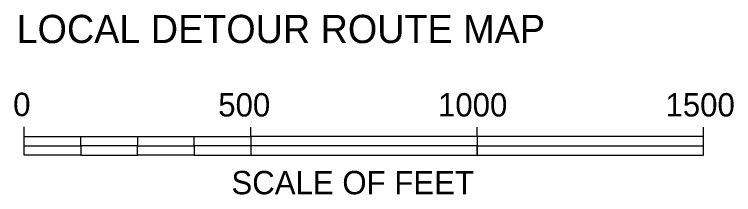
# Model space of a CAD drawing. Extents: x -452339 to 6403467, y -1 to 1814750.
# Drawn here: x -19225 to 6192, y 1556532 to 1562891 of the extents above; entities that cross this region are included whole.
import ezdxf

# ---------------------------------------------------------------- set-up
doc = ezdxf.new("R2010")
doc.units = 0
doc.layers.add('Default', color=7, linetype='Continuous')

msp = doc.modelspace()

# ---------------------------------------------------------------- linework, layer by layer
at = {"layer": 'Default'}
for p, q in [((-18873, 1558583), (-18873, 1558928)), ((-10873, 1558583), (-10873, 1558913)), ((-2874, 1558583), (-2874, 1558913)), ((5126, 1558583), (5126, 1558913)), ((-18873, 1558583), (-16873, 1558583)), ((-18873, 1558253), (-18873, 1558583)), ((-16873, 1558253), (-16873, 1558583)), ((-16873, 1558583), (-14873, 1558583)), ((-14874, 1558583), (-12873, 1558583)), ((-14874, 1558583), (-14874, 1558253)), ((-14873, 1558583), (-14873, 1558253)), ((-12873, 1558253), (-12873, 1558583)), ((-12873, 1558583), (-10873, 1558583)), ((-10873, 1558583), (-10873, 1558253)), ((-2874, 1558583), (-10873, 1558583)), ((-10873, 1558583), (-10873, 1558253)), ((5126, 1558583), (-2874, 1558583)), ((-2874, 1558583), (-2874, 1558253)), ((5126, 1558253), (5126, 1558583)), ((-18873, 1557923), (-18873, 1558253)), ((-18873, 1558253), (-16873, 1558253)), ((-16873, 1558253), (-16873, 1557923)), ((-14873, 1558253), (-16873, 1558253)), ((-16873, 1558253), (-16873, 1558253)), ((-14874, 1557923), (-14874, 1558253)), ((-14874, 1558253), (-12874, 1558253)), ((-14874, 1557923), (-14874, 1558253)), ((-12874, 1558253), (-12874, 1557923)), ((-10873, 1558253), (-12874, 1558253)), ((-12874, 1558253), (-12873, 1558253)), ((-2874, 1558253), (-10873, 1558253)), ((-10873, 1558253), (-10873, 1557923)), ((-2874, 1557923), (-2874, 1558253)), ((-2874, 1558253), (5126, 1558253)), ((-2874, 1558253), (-2874, 1557923)), ((5126, 1557923), (5126, 1558253)), ((-16873, 1557923), (-18874, 1557923)), ((-18874, 1557923), (-18873, 1557923)), ((-16873, 1557923), (-14874, 1557923)), ((-12874, 1557923), (-14874, 1557923)), ((-14874, 1557923), (-14874, 1557923)), ((-12874, 1557923), (-10874, 1557923)), ((-10873, 1557923), (-2874, 1557923)), ((-2874, 1557923), (5126, 1557923))]:
    msp.add_line(p, q, dxfattribs=at)

# ---------------------------------------------------------------- texts
for s, height, p in [('LOCAL DETOUR ROUTE MAP', 997.23, (-19146, 1561879)), ('0', 824, (-19268, 1559304)), ('500', 823.7, (-12020, 1559289)), ('1000', 823.7, (-4254, 1559289)), ('1500', 823.7, (3785, 1559289)), ('SCALE OF FEET', 823.68, (-11553, 1556544))]:
    msp.add_text(s, height=height, dxfattribs=at).set_placement(p)

doc.saveas('drawing.dxf')
